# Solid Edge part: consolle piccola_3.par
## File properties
Last saved by: i.fialdini
Revision: 62
Tipo di contenuto documento: 0
Accuracy: 0.990
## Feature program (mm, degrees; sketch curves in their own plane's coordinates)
body "unnamed Body 1"
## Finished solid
Body 1: solid body, 40 faces, 94 edges, 62 vertices, 1 internal void.
  Faces by surface: spline 18, cylinder 14, plane 8
  Edges by curve: curve on surface 72, circle 8, ellipse 8, line 4, spline 2
Bounding box of the edges (mm; curved faces can reach further): 64.552 x 416.669 x 749.548, from (-240.8356, -924.4912, -47.5677) to (-176.2834, -507.8225, 701.9805).
Cylindrical faces by radius (mm): R4.75 x2, R6.25 x2, R6.5 x1, R8 x1, R9 x2, R10.5 x6
Planar faces by outward normal: +x 2, +z 2, -z 2, oblique 2
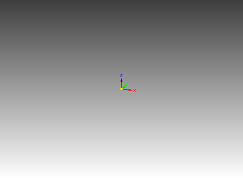
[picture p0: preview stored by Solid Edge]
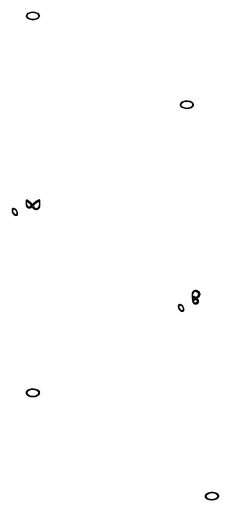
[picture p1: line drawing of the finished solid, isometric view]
